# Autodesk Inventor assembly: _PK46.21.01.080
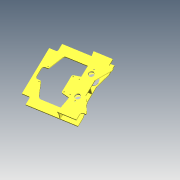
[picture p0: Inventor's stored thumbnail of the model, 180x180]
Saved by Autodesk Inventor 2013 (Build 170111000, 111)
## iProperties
Created: 2005-04
Part Number: _PK46.21.01.080
Document SubType Name: Assembly
Designer: salex
Manufacturer: Standard
Standards Organization: Custom
Author: salex
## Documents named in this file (5)
- D:\FrontLoaderVault\Data\Assy, Chassis, Front\_PK46.21.01.080.iam
- D:\FrontLoaderVault\Data\Assy, Chassis, Front\PK46.21.01.019.ipt
- D:\FrontLoaderVault\Data\Assy, Chassis, Front\PK46.21.01.022.ipt
- D:\FrontLoaderVault\Data\Assy, Chassis, Front\PK46.21.01.024.ipt
- D:\FrontLoaderVault\Data\Assy, Chassis, Front\_PK46.21.01.021.ipt
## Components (9 placed, 4 different names)
1. PK46.21.01.019:1 — Mate:6, Mate:7, Insert:1, Insert:4, Mate:18, Mate:19, Mate:20, Mate:21, Flush:3, Mate:22, Flush:4
2. _PK46.21.01.021:1 — Mate:6, Mate:7, Insert:2, Insert:3, Flush:1, Flush:2
3. PK46.21.01.022:1 — Insert:1
4. PK46.21.01.022:2 — Insert:2
5. PK46.21.01.022:3 — Insert:3
6. PK46.21.01.022:4 — Insert:4
7. PK46.21.01.024:1 — Mate:20, Flush:2, Mate:21
8. PK46.21.01.024:2 — Mate:18, Mate:19, Flush:1
9. PK46.21.01.024:3 — Flush:3, Mate:22, Flush:4
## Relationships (15: Mate 7, Insert 4, Flush 4)
- Mate:6: PK46.21.01.019:1 ↔ _PK46.21.01.021:1
- Mate:7: PK46.21.01.019:1 ↔ _PK46.21.01.021:1
- Insert:1: PK46.21.01.019:1 ↔ PK46.21.01.022:1
- Insert:2: _PK46.21.01.021:1 ↔ PK46.21.01.022:2
- Insert:3: _PK46.21.01.021:1 ↔ PK46.21.01.022:3
- Insert:4: PK46.21.01.019:1 ↔ PK46.21.01.022:4
- Mate:18: PK46.21.01.019:1 ↔ PK46.21.01.024:2
- Mate:19: PK46.21.01.019:1 ↔ PK46.21.01.024:2
- Flush:1: _PK46.21.01.021:1 ↔ PK46.21.01.024:2
- Mate:20: PK46.21.01.019:1 ↔ PK46.21.01.024:1
- Flush:2: _PK46.21.01.021:1 ↔ PK46.21.01.024:1
- Mate:21: PK46.21.01.019:1 ↔ PK46.21.01.024:1
- Flush:3: PK46.21.01.019:1 ↔ PK46.21.01.024:3
- Mate:22: PK46.21.01.019:1 ↔ PK46.21.01.024:3
- Flush:4: PK46.21.01.019:1 ↔ PK46.21.01.024:3
